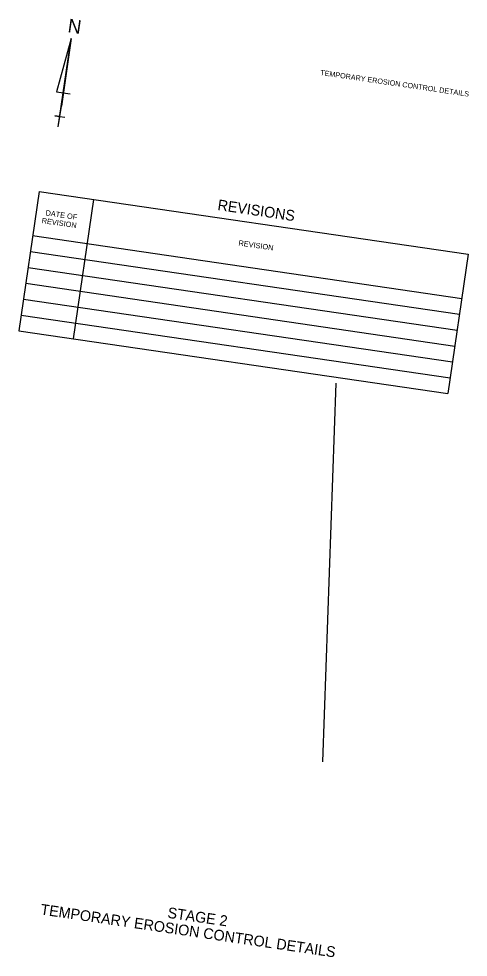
# Model space of a CAD drawing. Extents: x 882623 to 886086, y 1564278 to 1565583.
# Drawn here: x 885582 to 886086, y 1564278 to 1565331 of the extents above; entities that cross this region are included whole.
import ezdxf

# ---------------------------------------------------------------- set-up
doc = ezdxf.new("R2010")
doc.units = 0
for name, color, linetype in [('R_Annotation', 7, 'Continuous'), ('R_Border', 7, 'Continuous'), ('R_No Plot', 7, 'Continuous'), ('S_BASELINE', 7, 'Continuous')]:
    doc.layers.add(name, color=color, linetype=linetype)

msp = doc.modelspace()

# ---------------------------------------------------------------- linework, layer by layer
at = {"layer": 'R_Border'}
for p, q in [((885640.4, 1565308.6), (885623.9, 1565248.8)), ((885625.9, 1565209.6), (885640.4, 1565308.6)), ((885640.4, 1565308.6), (885629.3, 1565232.5)), ((885623.9, 1565248.8), (885639.1, 1565246.6)), ((885625.9, 1565209.6), (885629.3, 1565232.5)), ((885627.6, 1565221), (885621.9, 1565221.9)), ((885621.9, 1565221.9), (885633.3, 1565220.2)), ((885625.9, 1565209.6), (885627.6, 1565221))]:
    msp.add_line(p, q, dxfattribs=at)
at = {"layer": 'R_No Plot'}
msp.add_line((885922.9, 1564496.9), (885937.7, 1564921.7), dxfattribs=at)
at = {"layer": 'S_BASELINE'}
for p, q in [((885604.3, 1565136.8), (885581.5, 1564980.5)), ((885604.3, 1565136.8), (886086, 1565066.5)), ((885665.5, 1565127.9), (885642.7, 1564971.6)), ((885597.1, 1565087.4), (886078.8, 1565017)), ((885594.5, 1565069.5), (886076.2, 1564999.2)), ((886086, 1565066.5), (886063.2, 1564910.1)), ((885591.9, 1565051.7), (886073.6, 1564981.4)), ((885589.3, 1565033.9), (886071, 1564963.5)), ((885586.7, 1565016.1), (886068.4, 1564945.7)), ((885584.1, 1564998.3), (886065.8, 1564927.9)), ((885581.5, 1564980.5), (886063.2, 1564910.1))]:
    msp.add_line(p, q, dxfattribs=at)

# ---------------------------------------------------------------- texts
at = {"layer": 'R_Annotation'}
for s, p in [('TEMPORARY EROSION CONTROL DETAILS', (885605.3, 1564325.7)), ('STAGE 2', (885747.9, 1564322))]:
    msp.add_text(s, height=12, rotation=351.6881, dxfattribs=at).set_placement(p)
at = {"layer": 'R_Border'}
for s, height, rotation, p in [('N', 15.4, 351.6882, (885635.8, 1565315.7)), ('TEMPORARY EROSION CONTROL DETAILS', 5.862, 351.6881, (885919.6, 1565267.6))]:
    msp.add_text(s, height=height, rotation=rotation, dxfattribs=at).set_placement(p)
at = {"layer": 'S_BASELINE'}
for s, height, p in [('REVISIONS', 12, (885804.1, 1565116.2)), ('DATE OF', 6, (885611.2, 1565110.2)), ('REVISION', 6, (885606.9, 1565101.5)), ('REVISION', 6, (885827.8, 1565076.4))]:
    msp.add_text(s, height=height, rotation=351.6881, dxfattribs=at).set_placement(p)

doc.saveas('drawing.dxf')
